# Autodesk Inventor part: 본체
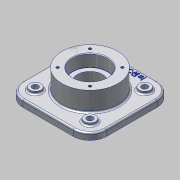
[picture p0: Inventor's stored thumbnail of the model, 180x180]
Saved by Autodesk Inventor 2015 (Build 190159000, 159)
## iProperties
Created: 2015-07
Part Number: 본체
Material: 알루미늄 6061
Document SubType Name: Modeling
Designer: AMC
Density: 2.7 g/cm^3
Appearance: 알루미늄 - 평지
Mass: 1459.27 g
Surface Area: 800.934 cm^2
Volume: 540.471 cm^3
Author: AMC
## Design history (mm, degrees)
sketch "스케치1"
  geometry: L1 (-75, -75)-(75, -75); L2 (75, -75)-(75, 75); L3 (75, 75)-(-75, 75); L4 (-75, 75)-(-75, -75); L5 (-75, -75)-(75, 75); L6 (75, -75)-(-75, 75); 1 further point
  constraints: 12 end point, 2 midpoint, 2 parallel, 1 horizontal, 1 perpendicular
  dimensions: "d0" = 150 distance of L3.end L2.end; "d1" = 150 distance of L2.end L1.end
extrude "돌출1" new body sketch "스케치1" distance "d2" = 12; taper "d3" = 0 deg
sketch "스케치2"
  geometry: C1 r 50 at (0, 0); 1 further point
  constraints: 1 centre point, 1 coincident
  dimensions: "d4" = 100 diameter of C1
extrude "돌출2" join sketch "스케치2" distance "d5" = 47; taper "d7" = 0 deg; dims "d6" = 23, "d8" = 0
sketch "스케치3"
  geometry: L1 (-75, 75)-(-75, -75) reference; L2 (75, -75)-(75, 75) reference; L3 (75, 75)-(-75, 75) reference; C1 r 10 at (-49, 49); C2 r 10 at (49, 49); C3 r 10 at (-49, -49); C4 r 10 at (49, -49); 1 further point
  constraints: 4 centre point, 2 vertical alignment, 1 horizontal alignment
  dimensions: "d9" = 20 diameter of C1; "d10" = 20 diameter of C2; "d11" = 20 diameter of C3; "d12" = 20 diameter of C4; "d13" = 26 distance from line of C1.centre L1; "d14" = 26 distance from line of C2.centre L2; "d15" = 98 distance of C2.centre C1.centre; "d16" = 98 distance of C4.centre C2.centre; "d17" = 26 distance from line of C2.centre L3
extrude "돌출3" join sketch "스케치3" distance "d18" = 5; taper "d19" = 0 deg
hole "구멍1" diameter "d22" = 11; stored, may be unused: countersink angle "d26" = 90 deg, drill point angle "d28" = 118 deg; dims "d20" = 10, "d21" = 10, "d23" = 6, "d24" = 4, "d25" = 2, "d27" = 8
hole "구멍2" diameter "d31" = 11; stored, may be unused: countersink angle "d35" = 90 deg, drill point angle "d37" = 118 deg; dims "d29" = 10, "d30" = 10, "d32" = 6, "d33" = 4, "d34" = 2, "d36" = 8
hole "구멍3" diameter "d40" = 11; stored, may be unused: countersink angle "d44" = 90 deg, drill point angle "d46" = 118 deg; dims "d38" = 10, "d39" = 10, "d41" = 6, "d42" = 4, "d43" = 2, "d45" = 8
hole "구멍4" diameter "d49" = 11; stored, may be unused: countersink angle "d53" = 90 deg, drill point angle "d55" = 118 deg; dims "d47" = 10, "d48" = 10, "d50" = 6, "d51" = 4, "d52" = 2, "d54" = 8
fillet "모깎기1" dims "d56" = 30
hole "구멍5" diameter "d59" = 45; stored, may be unused: countersink angle "d63" = 90 deg, drill point angle "d65" = 118 deg; dims "d57" = 10, "d58" = 10, "d60" = 6, "d61" = 62, "d62" = 22, "d64" = 8
hole "구멍6" diameter "d68" = 62; stored, may be unused: countersink angle "d72" = 90 deg, drill point angle "d74" = 0 deg; dims "d66" = 10, "d67" = 10, "d69" = 6, "d70" = 62, "d71" = 22, "d73" = 22
sketch "스케치4"
  geometry: L1 (0, 0)-(41, 0); L2 (0, 0)-(28.991, 28.991); A1 r 41 centre (0, 0) between (41, 0) and (28.991, 28.991); 1 further point
  constraints: 4 end point, 2 point on circle, 1 centre point, 1 coincident, 1 horizontal
  dimensions: "d75" = 82 diameter of A1; "d76" = 45 deg angle of L1 L2
hole "구멍7" sketch "스케치4" at (28.991, 28.991) diameter "d77" = 4.917; stored, may be unused: countersink angle "d81" = 90 deg, drill point angle "d83" = 118 deg; dims "d78" = 10, "d79" = 62, "d80" = 22, "d82" = 13
sketch "스케치5"
  geometry: L1 (0, 0)-(-41, 0); L2 (0, 0)-(-28.991, -28.991); A1 r 41 centre (0, 0) between (-41, 0) and (-28.991, -28.991); 1 further point
  constraints: 4 end point, 2 point on circle, 1 centre point, 1 coincident, 1 horizontal
  dimensions: "d87" = 82 diameter of A1; "d88" = 45 deg angle of L1 L2
hole "구멍8" sketch "스케치5" at (-28.991, -28.991) diameter "d89" = 4.917; stored, may be unused: countersink angle "d93" = 90 deg, drill point angle "d95" = 118 deg; dims "d90" = 10, "d91" = 62, "d92" = 22, "d94" = 13
fillet "모깎기2" dims "d99" = 0.3
chamfer "모따기1" distance "d100" = 1; stored, may be unused: second distance "d101" = 2, angle "d102" = 45 deg
sketch "스케치6"
  geometry: 2 further points
  constraints: 1 vertical alignment, 1 other
  dimensions: "d108" = 65 distance of point (0, 0) point (0, 65)
feature "엠보싱1" sketch "스케치6" dims "d0" = 150, "d1" = 150, "d103" = 1, "d104" = 0
fillet "모깎기3" dims "d105" = 3
fillet "모깎기4" dims "d106" = 3
fillet "모깎기5" dims "d107" = 3
node "솔리드1"
pattern_circular "원형 패턴1" dims angle "d85" = 360 deg
pattern_circular "원형 패턴2" dims angle "d97" = 360 deg
